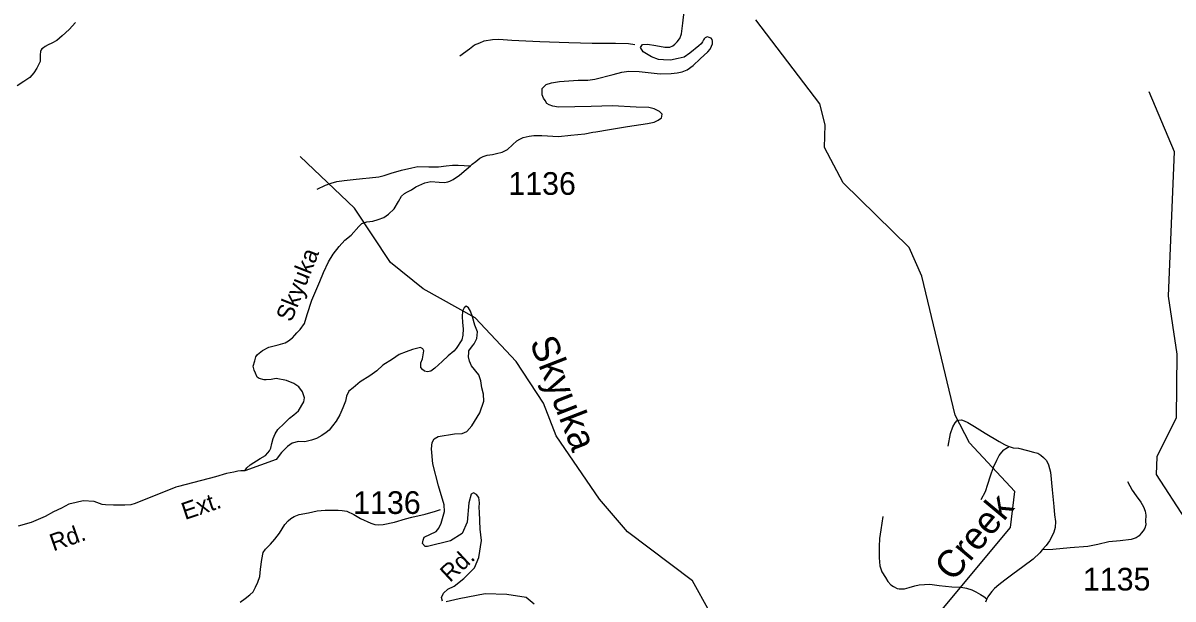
# Model space of a CAD drawing. Extents: x 990631 to 1056237, y 535999 to 585651.
# Drawn here: x 1032860 to 1039191, y 565244 to 568418 of the extents above; entities that cross this region are included whole.
import ezdxf

# ---------------------------------------------------------------- set-up
doc = ezdxf.new("R2010")
doc.units = 0
for name, color, linetype in [('Exist Hydrographic Creek Single Shore', 7, 'Continuous'), ('Exist Hydrographic Creek Single Shore Label', 7, 'Continuous'), ('Exist Road Non-System Type 51', 7, 'Continuous'), ('Exist Road Secondary Type 20 Attributed', 7, 'Continuous'), ('Exist Road Secondary Type 51 Attributed', 7, 'Continuous'), ('Exist Road Secondary Type 51 Label', 7, 'Continuous'), ('Exist Road Secondary Type 51 Number Label', 7, 'Continuous')]:
    doc.layers.add(name, color=color, linetype=linetype)

msp = doc.modelspace()

# ---------------------------------------------------------------- linework, layer by layer
at = {"layer": 'Exist Hydrographic Creek Single Shore'}
for points in [[(1037044.6, 563559.5), (1037169.3, 563750.7), (1037368.1, 564019.8), (1037559.1, 564054.9), (1037753.3, 564272.7), (1037776.9, 564488.9), (1037621.7, 564843.2), (1037624, 564918.6), (1037863.8, 565117.3), (1038297.5, 565637), (1038320.6, 565836.7), (1038070.8, 566104.3), (1037992.3, 566256.9), (1037808.4, 567022), (1037738.6, 567180.9), (1037374.6, 567536.2), (1037272.5, 567731.9), (1037276.5, 567856.5), (1037246.9, 567972), (1036894.9, 568435.2)], [(1039058.6, 568040.6), (1039198.1, 567709.6), (1039164.1, 566912.6), (1039212.2, 566593.3), (1039209.2, 566242.3), (1039102.3, 566027.8), (1039099.1, 565929.3), (1039258.1, 565683.3), (1039256.7, 565381.4), (1039368, 565057.5), (1039282.3, 564953.8), (1039235.5, 564805.6), (1039297.9, 564641.8), (1039239.4, 564474), (1039297.9, 564357), (1039453.6, 564241.8), (1039600.7, 564115)], [(1037044.6, 563559.5), (1037001.7, 563731.2), (1036908.1, 564082.2), (1036919.8, 564168), (1036993.9, 564242.1), (1036997.8, 564320.1), (1036814.6, 564515.1), (1036760, 564737.5), (1036787.3, 564827.2), (1036653.8, 565082.5), (1036640.1, 565174.8), (1036545.5, 565344), (1036187.2, 565613.8), (1036034.6, 565794.1), (1035795.7, 566143.5), (1035726.2, 566322.2), (1035575.2, 566551.7), (1035349.5, 566792.5), (1035062.6, 566952.6), (1034884.1, 567097.3), (1034685.1, 567396.6), (1034385.6, 567681.7)]]:
    msp.add_lwpolyline(points, dxfattribs=at)
at = {"layer": 'Exist Road Non-System Type 51'}
msp.add_line((1038166.4, 565245.3), (1038159.8, 565225.4), dxfattribs=at)
for points in [[(1033149, 568420.3), (1033113.6, 568381.4), (1033076.5, 568346.6), (1033045.8, 568321.6), (1033019.3, 568306.5), (1032998.9, 568297.1), (1032982.5, 568287.6), (1032972.4, 568281.8), (1032964.2, 568276.2), (1032959.9, 568270.3), (1032955.7, 568260.3), (1032955.2, 568242.3), (1032954, 568206.4), (1032947.5, 568190.7), (1032936.7, 568168.9), (1032920, 568143.4), (1032897, 568118.1), (1032864.4, 568095.1), (1032827.5, 568072.4)], [(1035264.4, 568236.3), (1035317.6, 568274.7), (1035346.5, 568297.7), (1035374.7, 568309), (1035399.1, 568320.1), (1035445.5, 568326.7), (1035479.6, 568329.5), (1035551.5, 568323.2), (1035705.2, 568316.3), (1035865.1, 568311.1), (1035993.1, 568307.1), (1036121.3, 568306.9), (1036193.1, 568304.7), (1036229, 568299.6)], [(1034480.4, 567503), (1034525, 567523.5), (1034557.5, 567534.5), (1034587.7, 567543.7), (1034628, 567550.3), (1034678.1, 567554.7), (1034728.5, 567561.1), (1034768.5, 567563.9), (1034818.7, 567570.2), (1034849, 567577.2), (1034887.5, 567590.1), (1034944, 567606.1), (1035000.5, 567620.4), (1035034.7, 567627.3), (1035094.7, 567625.3), (1035146.7, 567625.7), (1035189, 567630.4), (1035225.1, 567635.3), (1035255.1, 567634.3), (1035289.1, 567633.2), (1035323, 567630.1)], [(1037953.3, 566086.7), (1037965.5, 566156.3), (1037978.6, 566192), (1037991.3, 566213.6), (1038003.7, 566227.1), (1038011.8, 566229), (1038027.8, 566230.4), (1038041.7, 566226), (1038061.5, 566215.4), (1038098.7, 566194), (1038157.6, 566158.2), (1038234.3, 566111.7), (1038263.8, 566094.7), (1038287.3, 566084), (1038289.3, 566083.9)], [(1038135.8, 565792.7), (1038159.3, 565835.9), (1038172.5, 565875.6), (1038186.1, 565923.2), (1038203.6, 565970.6), (1038220.8, 566008.1), (1038233.7, 566033.6), (1038248.3, 566053.2), (1038260.8, 566064.9), (1038270.9, 566072.5), (1038289.3, 566083.9)], [(1038289.3, 566083.9), (1038311.2, 566077.3), (1038341.2, 566074.3), (1038390.7, 566062.7), (1038422.4, 566053.7), (1038446.3, 566047), (1038463.8, 566036.2), (1038477.6, 566023.9), (1038495.1, 566007.2), (1038506.2, 565982.9), (1038517, 565942.5), (1038525.8, 565846.1), (1038535, 565753.9), (1038539.5, 565707.6), (1038544.3, 565671.5), (1038543.3, 565637.5), (1038534.3, 565611.8), (1038523.7, 565588), (1038510.8, 565564.5), (1038492.1, 565539.1), (1038471.1, 565513.7)], [(1038941.5, 565891), (1038966.1, 565844), (1038989.1, 565811.4), (1039014, 565776.5), (1039029.1, 565751.9), (1039038.4, 565727.7), (1039041.8, 565705.5), (1039040.7, 565673.5), (1039041.9, 565651.5), (1039035.3, 565633.8), (1039027.1, 565619.9), (1039016.6, 565606.3), (1039004.1, 565592.6), (1038987.7, 565581.1), (1038961.5, 565572), (1038901.1, 565564), (1038838.7, 565557.9), (1038778.2, 565543.9), (1038722, 565533.6), (1038625.6, 565524.8), (1038529.2, 565515.9), (1038471.1, 565513.7)], [(1034055.1, 565227.1), (1034083.7, 565246.1), (1034108.5, 565267.4), (1034127.1, 565282.9), (1034139.8, 565308.4), (1034152.7, 565336), (1034163.8, 565367.6), (1034167, 565407.5), (1034174.7, 565461.4), (1034182, 565499.3), (1034194.6, 565518.8), (1034209.1, 565532.3), (1034223.6, 565545.8), (1034246.3, 565573.2), (1034271.4, 565606.3), (1034301, 565653.5), (1034319.6, 565675), (1034334, 565686.5), (1034352.5, 565697.9), (1034380.7, 565708.9), (1034431.1, 565719.3), (1034479.6, 565729.8), (1034523.6, 565732.3), (1034561.6, 565733.1), (1034595.7, 565734), (1034617.6, 565731.4), (1034643.6, 565728.5), (1034681, 565709.3), (1034718.4, 565688.1), (1034775.5, 565662.2), (1034797.3, 565653.5), (1034815.3, 565653), (1034843.4, 565654), (1034905.8, 565666.2), (1034966.4, 565686.2), (1035000.8, 565695.1), (1035073.4, 565710.8), (1035131.9, 565726.9), (1035158.1, 565736.1)], [(1037594.6, 565698), (1037582.1, 565624.4), (1037574.7, 565576.5), (1037573.2, 565532.5), (1037573.2, 565470.5), (1037577.9, 565426.2), (1037588.8, 565394), (1037607.8, 565361.4), (1037621, 565340.9), (1037638.4, 565322.3), (1037652.2, 565311.8), (1037671.8, 565301.3), (1037683.8, 565298.8), (1037713.8, 565299.8), (1037738.1, 565307.1), (1037770.3, 565316.1), (1037794.6, 565321.2), (1037852.7, 565325.4), (1037904.6, 565317.8), (1037974.3, 565311.6), (1038024.3, 565309.8), (1038054.2, 565303), (1038083.8, 565294), (1038105.6, 565283.3), (1038131.1, 565268.4), (1038150.7, 565257.8), (1038166.4, 565245.3)], [(1038471.1, 565513.7), (1038458.6, 565498.1), (1038421.5, 565463.2), (1038364.2, 565421), (1038308.8, 565380.9), (1038265.7, 565348.1), (1038232.8, 565321.2), (1038208.2, 565301.9), (1038193.6, 565284.4), (1038181.1, 565268.8), (1038172.6, 565255.2), (1038166.4, 565245.3)]]:
    msp.add_lwpolyline(points, dxfattribs=at)
at = {"layer": 'Exist Road Secondary Type 20 Attributed'}
for points in [[(1036474.1, 568329.7), (1036475.4, 568333.1), (1036485, 568357.3), (1036493.1, 568417.1), (1036500.9, 568481)], [(1035445.2, 567694.1), (1035467.3, 567699.5), (1035497.6, 567706.5), (1035528.1, 567721.6), (1035554.9, 567746.7), (1035579.5, 567768), (1035595.9, 567777.5), (1035614.3, 567786.9), (1035646.4, 567793.9), (1035672.5, 567797), (1035716.5, 567797.5), (1035808.5, 567792.6), (1035876.9, 567800.5), (1035953, 567807.9), (1035997.4, 567816.7), (1036013.5, 567818.1), (1036089.8, 567830.5), (1036187.6, 567847.5), (1036299.1, 567863.7), (1036334.8, 567871.3), (1036356.9, 567882.4), (1036369.7, 567890.9), (1036374.8, 567893.5), (1036379, 567914.7), (1036364.6, 567930.9), (1036335.7, 567944.5), (1036305, 567951.4), (1036236.1, 567954.8), (1036105.1, 567960.7), (1035987.7, 567958.2), (1035807.7, 567954.7), (1035777.8, 567959.7), (1035756.1, 567966.4), (1035744.3, 567974.8), (1035734.2, 567990.5), (1035725.7, 568004.1), (1035718.9, 568021.2), (1035718.9, 568056.1), (1035740.1, 568079), (1035769.9, 568088.4), (1035813.3, 568095.2), (1035917.1, 568102.9), (1035969, 568103.7), (1036009, 568108.8), (1036109.4, 568134.4), (1036157, 568147.1), (1036196.1, 568153.1), (1036252.3, 568149.7), (1036367.1, 568136.9), (1036429.2, 568139.5), (1036460.7, 568143.7), (1036489.6, 568148.8), (1036516, 568159.9), (1036549.2, 568183.7), (1036588.3, 568221.2), (1036629.9, 568258.7), (1036642.4, 568274.3), (1036650.9, 568289.9), (1036655.4, 568303.8), (1036655.9, 568317.8), (1036654.3, 568327.8), (1036648.4, 568334.2), (1036638.5, 568338.4), (1036628.6, 568340.8), (1036622.5, 568338.9), (1036616.5, 568337), (1036610.4, 568331.3), (1036606, 568325.4), (1036601.8, 568313.5), (1036593.4, 568303.9), (1036581, 568292.1), (1036531.7, 568251.7), (1036500.9, 568228.7), (1036466.7, 568221.8), (1036424.3, 568213.2), (1036386.3, 568214.4), (1036358.6, 568217.3), (1036320.8, 568230.5), (1036273.8, 568258.1), (1036259.9, 568283.3), (1036271, 568299.5), (1036297.4, 568300.4), (1036343.3, 568293.6), (1036392.8, 568284.3), (1036420.8, 568285.3), (1036436.9, 568292.8), (1036449.3, 568300.4), (1036461.6, 568314.1), (1036474.1, 568329.7)], [(1034081.7, 565950.5), (1034092.8, 565966.4), (1034111.5, 565983.9), (1034166.6, 566018), (1034195.2, 566035.2), (1034207.5, 566048.8), (1034217.9, 566060.3), (1034224.4, 566074.2), (1034229.3, 566100.1), (1034238.1, 566127.8), (1034249, 566153.6), (1034263.7, 566177.1), (1034298.7, 566210), (1034327.8, 566241), (1034351.3, 566257.8), (1034376.8, 566279.9), (1034405.8, 566329.3), (1034409.2, 566353.1), (1034398.9, 566385.5), (1034378.5, 566412.7), (1034351.3, 566431.4), (1034310.5, 566448.5), (1034254.3, 566458.7), (1034226.7, 566454), (1034198.6, 566451.4), (1034188.4, 566452.3), (1034160.3, 566459.1), (1034150.1, 566465.9), (1034140.7, 566488), (1034133.1, 566504.2), (1034127.1, 566526.4), (1034135.6, 566557), (1034142.5, 566578.3), (1034151, 566591), (1034178.2, 566614), (1034213.1, 566631.9), (1034265, 566644.7), (1034304.1, 566655.7), (1034321.1, 566666), (1034338.1, 566678.7), (1034344.1, 566682.8), (1034356, 566697.5), (1034366.8, 566710), (1034385.8, 566729), (1034409.6, 566761.3), (1034424, 566810.7), (1034449.6, 566890.7), (1034493.8, 566992.8), (1034515.1, 567042.2), (1034541.5, 567100.8), (1034566.8, 567143.9), (1034600.3, 567186.9), (1034631.4, 567221.9), (1034666.4, 567248.8), (1034709, 567295.9), (1034726.1, 567313.8), (1034752.4, 567322.3), (1034786.5, 567326.5), (1034816.2, 567334.2), (1034846.9, 567346.1), (1034873.2, 567364.8), (1034903, 567393.8), (1034926.8, 567433.8), (1034943.8, 567462.7), (1034959.9, 567477.6), (1034976.2, 567487), (1034998.5, 567498.4), (1035023, 567514.7), (1035072.3, 567536.8), (1035105.5, 567543.6), (1035150.6, 567540.2), (1035180.4, 567539.3), (1035199.1, 567542.8), (1035210.3, 567545.6), (1035228.5, 567555), (1035263.4, 567579.9), (1035300.4, 567610.8), (1035323, 567630.1), (1035333.2, 567639.7), (1035353.8, 567655.1), (1035374.3, 567672.5), (1035392.7, 567682), (1035415.1, 567689.1), (1035445.2, 567694.1)]]:
    msp.add_lwpolyline(points, dxfattribs=at)
at = {"layer": 'Exist Road Secondary Type 51 Attributed'}
for points in [[(1035314.4, 566611.7), (1035335.3, 566638.9), (1035343.6, 566650.7), (1035359, 566678.7), (1035362.4, 566715.3), (1035347.1, 566751.9), (1035335.2, 566798.8), (1035323.3, 566829.4), (1035313.1, 566849), (1035299.5, 566857.5), (1035288.4, 566848.1), (1035279, 566829.4), (1035278.2, 566801.3), (1035279, 566767.3), (1035284.1, 566732.4), (1035281.6, 566697.5), (1035275.6, 566671.9), (1035244.2, 566624.2), (1035231.4, 566609.8), (1035201.6, 566583.4), (1035167.6, 566552.7), (1035127.6, 566515.3), (1035104.6, 566500), (1035087.6, 566494.9), (1035070.6, 566500), (1035058.7, 566508.5), (1035050.2, 566519.5), (1035051, 566545.9), (1035058.8, 566567.8), (1035067.2, 566611.5), (1035061.2, 566622.5), (1035048.5, 566629.4), (1035004.2, 566619.1), (1034969.4, 566606.4), (1034931.9, 566591), (1034893.7, 566565.5), (1034840.9, 566531.5), (1034808.6, 566501.7), (1034770.3, 566474.4), (1034715.8, 566441.2), (1034677.6, 566407.2), (1034653.7, 566388.4), (1034641, 566362.1), (1034635, 566333.1), (1034621.8, 566297.5), (1034604.6, 566258), (1034583.5, 566222.9), (1034564.6, 566197.4), (1034545.7, 566174), (1034529.4, 566160.5), (1034504.9, 566145.2), (1034476.4, 566128.2), (1034448, 566119.1), (1034411.8, 566110.3), (1034376.8, 566111.4), (1034341.1, 566102.9), (1034315.6, 566084.1), (1034283.2, 566051.8), (1034254.3, 566012.6), (1034081.7, 565950.5)], [(1035170.1, 565232.4), (1035165, 565251.2), (1035174.4, 565275), (1035198.6, 565297.6), (1035234.4, 565314.6), (1035287.1, 565357.2), (1035345, 565415), (1035369.9, 565473.2), (1035384.1, 565566.6), (1035377.3, 565627.8), (1035373.9, 565721.5), (1035372.2, 565748.7), (1035373.9, 565774.3), (1035368.8, 565803.2), (1035356.9, 565820.2), (1035339.9, 565828.7), (1035326.7, 565820.7), (1035314.8, 565773.8), (1035306.3, 565666.6), (1035278.2, 565605.3), (1035213.5, 565564.4), (1035087.6, 565532.1), (1035074.9, 565532.9), (1035059.5, 565549.1), (1035062.9, 565568.7), (1035068.1, 565584), (1035134.3, 565614.8), (1035149.7, 565634.2), (1035162.5, 565661.5), (1035181.2, 565726.2), (1035179.5, 565761.9), (1035147.1, 565868.1), (1035115.7, 565988.4), (1035108.9, 566070.9), (1035112.3, 566105.8), (1035124.2, 566127.1), (1035146.3, 566139), (1035234.8, 566154.4), (1035278.2, 566155.2), (1035302.9, 566167.1), (1035331.8, 566197.8), (1035375.2, 566269.3), (1035397.3, 566334), (1035394.7, 566373.1), (1035385.4, 566407.2), (1035380.3, 566445.5), (1035369.2, 566478.7), (1035329.2, 566528.1), (1035319, 566554.4), (1035313.1, 566577.4), (1035314.8, 566602.1), (1035314.4, 566611.7)], [(1034081.7, 565950.5), (1034060.2, 565949.5), (1034042.2, 565948), (1034020.1, 565942.7), (1033980.4, 565936), (1033919.1, 565917.3), (1033716.7, 565862.8), (1033701.3, 565859.4), (1033476.8, 565769.2), (1033454.6, 565762.4), (1033420.6, 565760.6), (1033357.6, 565760.6), (1033315.1, 565762.4), (1033296.4, 565764.1), (1033252.2, 565781.1), (1033190.9, 565784.5), (1033153.5, 565776), (1033112.6, 565765.8), (1033071.8, 565743.6), (1033027.6, 565723.2), (1032981.6, 565697.7), (1032905.1, 565665.3), (1032833.6, 565644.9)], [(1035674, 565215.1), (1035629.4, 565251.8), (1035523.3, 565267.7), (1035404.5, 565272), (1035261.6, 565244.8), (1035188.9, 565228.2)]]:
    msp.add_lwpolyline(points, dxfattribs=at)

# ---------------------------------------------------------------- texts
at = {"layer": 'Exist Hydrographic Creek Single Shore Label'}
for s, rotation, p in [('Skyuka', 291.26086, (1035647.8, 566659.3)), ('Creek', 50.15554, (1037980.5, 565334))]:
    msp.add_text(s, height=150, rotation=rotation, dxfattribs=at).set_placement(p)
at = {"layer": 'Exist Road Secondary Type 51 Label'}
for s, rotation, p in [('Skyuka', 68.37995, (1034338.1, 566765.3)), ('Ext.', 18.62927, (1033751.9, 565678.5)), ('Rd.', 19.23705, (1033027.4, 565505.7)), ('Rd.', 42.89419, (1035210.5, 565331.7))]:
    msp.add_text(s, height=95, rotation=rotation, dxfattribs=at).set_placement(p)
at = {"layer": 'Exist Road Secondary Type 51 Number Label'}
for s, p in [('1136', (1035532, 567470.9)), ('1136', (1034677.8, 565712.5)), ('1135', (1038695.2, 565290.5))]:
    msp.add_text(s, height=125, dxfattribs=at).set_placement(p)

doc.saveas('drawing.dxf')
